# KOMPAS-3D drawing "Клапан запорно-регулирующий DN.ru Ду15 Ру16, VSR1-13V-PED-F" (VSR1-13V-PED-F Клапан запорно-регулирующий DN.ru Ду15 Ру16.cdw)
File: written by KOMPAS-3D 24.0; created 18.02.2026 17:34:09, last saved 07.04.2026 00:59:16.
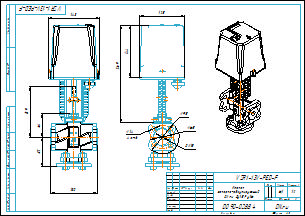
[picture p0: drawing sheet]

Document properties: Автор: R2D2; Форматы листов документа: A3; Полное имя файла: VSR1-13V-PED-F Клапан запорно-регулирующий DN.ru Ду15 Ру16.m3d; Масса: 6.1; Наименование: Клапан запорно-регулирующий DN.ru Ду15 Ру16; Количество листов документа: 1; Примечание: D090-02884

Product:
- Part/product: Клапан запорно-регулирующий DN.ru Ду15 Ру16  | designation VSR1-13V-PED-F
    Масса: 6.1
    Раздел спецификации: Прочие изделия
    Форматы листов документа: A3
    Примечание: D090-02884

Views: Вид 1, Спереди
Referenced files in E:\Работа\Зайцев\Солянка\VSR1-13V-PED-F Клапан запорно-регулирующий DN.ru\DN15\DN15 Kv0.16\: VSR1-13V-PED-F Клапан запорно-регулирующий DN.ru Ду15 Ру16.m3d
Referenced files in E:\Работа\Зайцев\Для компаса\: чертеж DN.ru А3.cdt
Referenced files in E:\Работа\Зайцев\Солянка\VSR1-13V-PED-F Клапан запорно-регулирующий DN.ru\DN15\DN15 Kv1\: VSR1-13V-PED-F Клапан запорно-регулирующий DN.ru Ду15 Ру16.m3d
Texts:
  Линейный размер
  VSR1-13V-PED-F
  чертеж DN.ru А3.cdt
  Клапан
  запорно-регулирующий
  DN.ru Ду15 Ру16
  Клапан запорно-регулирующий DN.ru Ду15 Ру16
  VSR1-13V-PED-F Клапан запорно-регулирующий DN.ru Ду15 Ру16
Dimensions and other numbers on the sheet: 0; 3; 2; 4; 130; 82; 143; 64; 139; 1:2; 1; 6,1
